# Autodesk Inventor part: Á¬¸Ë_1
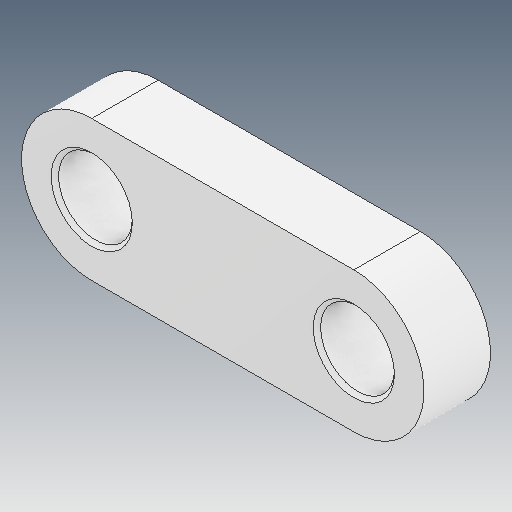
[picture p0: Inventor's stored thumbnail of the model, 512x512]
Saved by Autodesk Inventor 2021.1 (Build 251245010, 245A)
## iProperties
Created: 2021-05
Part Number: Á¬¸Ë_1
Material: Ogólny
Document SubType Name: Modeling
Designer: user
Density: 1 g/cm^3
Appearance: Domyślna
Author: user
Revision Number: ÈÎºÎ
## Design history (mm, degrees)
feature "ÊäÈë1"
node "Bryła1"
